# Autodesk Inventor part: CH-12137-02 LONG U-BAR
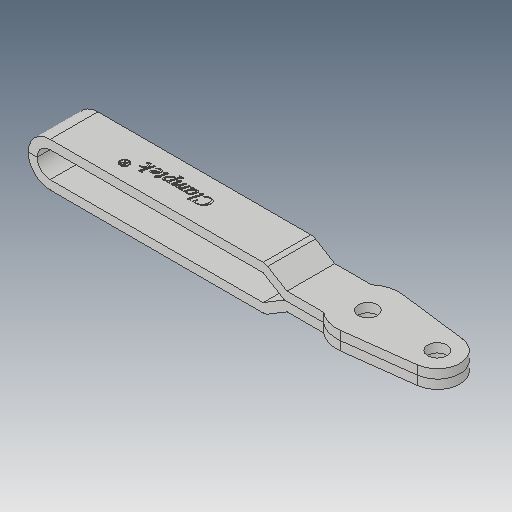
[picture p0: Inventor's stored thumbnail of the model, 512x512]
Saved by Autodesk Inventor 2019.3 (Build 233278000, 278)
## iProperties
Created: 2012-09
Part Number: CH-12137-02 LONG U-BAR
Material: Ogólny
Document SubType Name: Modeling
Designer: CADENGINEERING4
Density: 1 g/cm^3
Appearance: Domyślna
Author: CADENGINEERING4
Revision Number: ÈÎºÎ
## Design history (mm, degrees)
feature "ÇÐ³ý-À­Éì2"
feature "ÇÐ³ý-À­Éì6"
node "Bryła1"
node "Bryła2"
